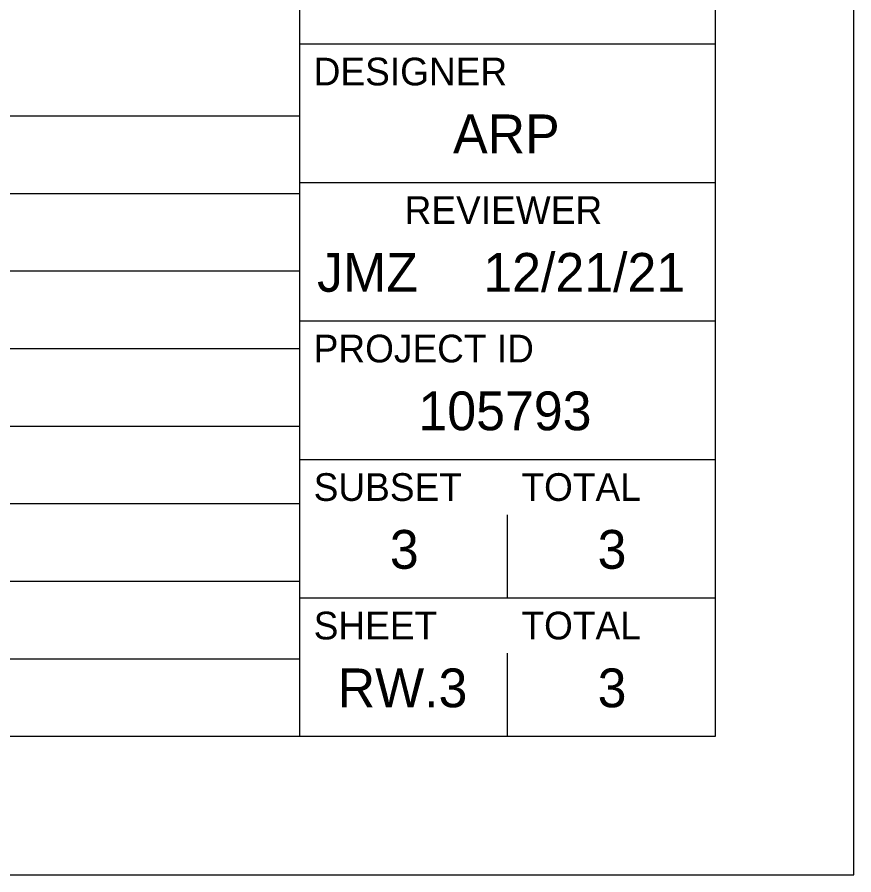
# Model space of a CAD drawing. Extents: x 54.5 to 92.3, y 4.7 to 26.7.
# Drawn here: x 85.503 to 88.523, y 4.717 to 7.813 of the extents above; entities that cross this region are included whole.
import ezdxf

# ---------------------------------------------------------------- set-up
doc = ezdxf.new("R2010")
doc.units = 0
for name, color, linetype in [('SH_Border', 7, 'Continuous'), ('SH_Cut_Line', 7, 'Continuous'), ('SH_Data', 7, 'Continuous'), ('SH_Text', 7, 'Continuous')]:
    doc.layers.add(name, color=color, linetype=linetype)

msp = doc.modelspace()

# ---------------------------------------------------------------- linework, layer by layer
at = {"layer": 'SH_Border'}
for p, q in [((86.5231, 5.2167), (86.5231, 26.2167)), ((86.5231, 7.7167), (88.0231, 7.7167)), ((86.5231, 7.2167), (88.0231, 7.2167)), ((86.5231, 6.7167), (88.0231, 6.7167)), ((86.5231, 6.2167), (88.0231, 6.2167)), ((86.5231, 5.7167), (88.0231, 5.7167))]:
    msp.add_line(p, q, dxfattribs=at)
msp.add_lwpolyline([(56.0231, 26.2167), (88.0231, 26.2167), (88.0231, 5.2167), (56.0231, 5.2167)], close=True, dxfattribs=at)
at = {"layer": 'SH_Cut_Line'}
msp.add_lwpolyline([(54.5231, 4.7167), (88.5231, 4.7167), (88.5231, 26.7167), (54.5231, 26.7167)], close=True, dxfattribs=at)
at = {"layer": 'SH_Data'}
for p, q in [((87.2731, 5.7167), (87.2731, 6.0167)), ((87.2731, 5.2167), (87.2731, 5.5167)), ((86.8981, 5.3917), (86.8981, 5.3917))]:
    msp.add_line(p, q, dxfattribs=at)
at = {"layer": 'SH_Text'}
for p, q in [((79.7197, 7.4567), (86.5231, 7.4567)), ((79.7197, 7.1767), (86.5231, 7.1767)), ((79.7197, 6.8967), (86.5231, 6.8967)), ((79.7197, 6.6167), (86.5231, 6.6167)), ((79.7197, 6.3367), (86.5231, 6.3367)), ((79.7197, 6.0567), (86.5231, 6.0567)), ((79.7197, 5.7767), (86.5231, 5.7767)), ((79.7197, 5.4967), (86.5231, 5.4967)), ((86.5231, 5.2167), (86.5231, 5.2167))]:
    msp.add_line(p, q, dxfattribs=at)

# ---------------------------------------------------------------- texts
at = {"layer": 'SH_Data'}
for s, height, p in [('DESIGNER', 0.1, (86.5731, 7.5667)), ('ARP', 0.14, (87.0763, 7.3217)), ('REVIEWER', 0.1, (86.9014, 7.0667)), ('12/21/21', 0.14, (87.1856, 6.8217)), ('JMZ', 0.14, (86.5854, 6.8217)), ('PROJECT ID', 0.1, (86.5731, 6.5667)), ('105793', 0.14, (86.9514, 6.3217)), ('SUBSET', 0.1, (86.5731, 6.0667)), ('TOTAL', 0.1, (87.3231, 6.0667)), ('3', 0.14, (86.8482, 5.8217)), ('3', 0.14, (87.5982, 5.8217)), ('SHEET', 0.1, (86.5731, 5.5667)), ('TOTAL', 0.1, (87.3231, 5.5667)), ('RW.3', 0.14, (86.6599, 5.3217)), ('3', 0.14, (87.5982, 5.3217))]:
    msp.add_text(s, height=height, dxfattribs=at).set_placement(p)

doc.saveas('drawing.dxf')
